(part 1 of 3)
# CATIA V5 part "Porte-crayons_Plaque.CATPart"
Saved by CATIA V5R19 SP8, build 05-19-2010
Part number: Plaque_Pot_Crayons
Material "Bleu vert": density 7860 kg/m3, Young's modulus 2e+11 Pa, Poisson ratio 0.266
Bounding box of the stored display mesh (mm): x -3 to 0, y -80 to 70, z 0 to 100
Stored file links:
  D:\Documents\1_Travail\1 - ac-limoges.fr\OneDrive - ac-limoges.fr\STI2D_Turgot\3 - Supports\Pot_à_Crayons\Maquette numérique\Maquette_eleve\Porte-crayons_Plaque.CATPart
  D:\Documents\1_Travail\1 - ac-limoges.fr\OneDrive - ac-limoges.fr\STI2D_Turgot\3 - Supports\Pot_à_Crayons\Maquette numérique\Maquette_eleve\Pot_Crayons.CATProduct
  D:\Documents\1_Travail\1 - ac-limoges.fr\OneDrive - ac-limoges.fr\STI2D_Turgot\3 - Supports\Pot_à_Crayons\Maquette numérique\Maquette_eleve\Porte-crayons_Pieds.CATPart
  D:\Documents\1_Travail\1 - ac-limoges.fr\OneDrive - ac-limoges.fr\STI2D_Turgot\3 - Supports\Pot_à_Crayons\Maquette numérique\Porte-crayons.CATPart
  C:\Program Files\Dassault Systemes\B19\win_b64\startup\materials\French\Catalog.CATMaterial
  D:\Documents\1_Travail\1 - ac-limoges.fr\OneDrive - ac-limoges.fr\STI2D_Turgot\3 - Supports\Pot_à_Crayons\Maquette numérique\Maquette_eleve\0-Pot_Crayons.CATProduct
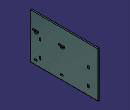
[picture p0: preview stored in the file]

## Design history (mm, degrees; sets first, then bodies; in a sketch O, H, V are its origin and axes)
SheetMetalParameters1: Thickness 3, BendRadius 4, KFactor 0.356492 {= log(min(100,max(20*SheetMetalParameters1.BendRadius,SheetMetalParameters1.Thickness)/SheetMetalParameters1.Thickness))/log(100)/2}, ReliefRadialLength 1, ReliefAxialLength 2, MinimumBendRadius 0
Set1
  DatumSurface1 to DatumSurface7: linked copy from another document
Body1 "Plaque" (main body), material "Bleu vert"
  AxisSystem1: origin (0, 0, 0), X (1, 0, 0), Y (0, 1, 0), Z (0, 0, 1)
  Sketch1 on YZ plane of AxisSystem1, origin (0, 0, 0), H (0, 1, 0), V (0, 0, 1)
    point P1 (0, 50)
    line L1 (70, 100) -> (70, 0)
    line L2 (70, 0) -> (-80, 0)
    line L3 (-80, 0) -> (-80, 100)
    line L4 (-80, 100) -> (70, 100)
    distance L4 L2 = 100
    distance V L1 = 70
    distance L3 V = 80
    vertical: L1 V, L3 V
    horizontal: L2 H, L4 H
    equidistance: L2 L4 P1
    coincidence: P1 V, L2 H
  Wall1: Thickness 3, Profile Sketch1
  Sketch2 on face of Wall1, origin (0, 0, 0), H (0, 1, 0), V (0, 0, 1)
    line L1 (-72, 64) -> (-72, 60)
    line L2 (-72, 60) -> (-66, 60)
    line L3 (-66, 60) -> (-66, 64)
    line L4 (-66, 64) -> (-62.5, 64)
    line L5 (-62.5, 64) -> (-62.5, 67)
    line L6 (-62.5, 67) -> (-75.5, 67)
    line L7 (-75.5, 67) -> (-75.5, 64)
    line L8 (-75.5, 64) -> (-72, 64)
    line L9 (-66, 8) -> (-72, 8)
    line L10 (-72, 8) -> (-72, 11)
    line L11 (-72, 11) -> (-66, 11)
    line L12 (-66, 11) -> (-66, 8)
    reference intersected line E1 (-72, 60) -> (-72, 63) from face of DatumSurface1
    reference intersected line E2 through (0, 63) direction (1, 0) from face of DatumSurface2
    reference intersected line E3 through (0, 11) direction (-1, 0) from face of DatumSurface3
    distance L6 L8 = 3 {= SheetMetalParameters1.Thickness}
    distance L8 L2 = 4 {= `détruit_LENGTH` +Sketch2.distance(L6 L8)}
    distance L1 L3 = 6 {= SheetMetalParameters1.Thickness *2}
    distance L11 L9 = 3 {= SheetMetalParameters1.Thickness}
    distance L7 L1 = 3.5 {= SheetMetalParameters1.Thickness +0.5mm}
    distance L8 E2 = 1
    distance L5 L3 = 3.5 {= SheetMetalParameters1.Thickness +0.5mm}
    horizontal: L2 H, L4 H, L8 H, L9 H, L11 H
    vertical: L1 V, L3 V, L5 V, L7 V, L10 V, L12 V
    coincidence: L4 L8, L12 L3, L1 L10, L1 E1, L11 E3
  CutOut1 "Découpe Accroche Ratelier": Direction Sketch2, EndLimit through (limit type 2), Orientation true, Profile Sketch2, StartLimit through (limit type 2)
  RectPattern1: of CutOut1, direction 1 instances 2, spacing 58, along edge [face of Wall1 | face of Wall1]
  Sketch3 on face of Wall1, origin (-3, 0, 0), H (0, -1, 0), V (0, 0, 1)
    line L1 (57, 57) -> (60, 57)
    line L2 (60, 57) -> (60, 51)
    line L3 (60, 51) -> (57, 51)
    line L4 (57, 51) -> (57, 57)
    point P5 (57, 21)
    line L5 (57, 21) -> (60, 21)
    line L6 (60, 21) -> (60, 15)
    line L7 (60, 15) -> (57, 15)
    line L8 (57, 15) -> (57, 21)
    point P7 (60, 15)
    point P9 (-50, 57)
    line L9 (-50, 57) -> (-47, 57)
    line L10 (-47, 57) -> (-47, 51)
    line L11 (-47, 51) -> (-50, 51)
    line L12 (-50, 51) -> (-50, 57)
    point P11 (-47, 51)
    point P13 (-50, 21)
    line L13 (-50, 21) -> (-47, 21)
    line L14 (-47, 21) -> (-47, 15)
    line L15 (-47, 15) -> (-50, 15)
    line L16 (-50, 15) -> (-50, 21)
    point P15 (-47, 15)
    reference intersected line E1 through (60, 0) direction (0, 1) from face of DatumSurface4
    reference intersected line E2 through (-50, 0) direction (0, 1) from face of DatumSurface5
    reference intersected line E3 (57, 57) -> (60, 57) from face of DatumSurface6
    reference intersected line E4 (57, 21) -> (60, 21) from face of DatumSurface7
    distance L4 L2 = 3 {= SheetMetalParameters1.Thickness}
    distance L12 L10 = 3 {= SheetMetalParameters1.Thickness}
    distance L1 L3 = 6 {= SheetMetalParameters1.Thickness *2}
    distance L5 L7 = 6 {= Sketch3.distance(L1 L3)}
    horizontal: L1 H, L3 H, L5 H, L7 H, L9 H, L11 H, L13 H, L15 H
    vertical: L2 V, L4 V, L6 V, L8 V, L10 V, L12 V, L14 V, L16 V
    coincidence: P5 L4, P7 L2, P9 L1, P11 L3, P13 L12, P13 L5, P15 L10, P15 L7, L2 E1, L12 E2, L1 E3, L5 E4
  CutOut2 "Découpe Accroche pieds": Direction Sketch3, EndLimit through (limit type 2), Orientation false, Profile Sketch3, StartLimit through (limit type 2)
  Sketch4 on face of Wall1, origin (-3, 0, 0), H (0, -1, 0), V (0, 0, 1)
    arc A1 centre (45.9101, 91.2592) radius 3.3 from (48.2435, 93.5926) to (48.0217, 93.7951) ccw
    line L1 (41.5489, 89.0193) -> (46.9279, 94.3983)
    line L2 (37.3062, 89.0193) -> (42.7281, 94.4411)
    line L3 (47.8494, 95.3198) -> (50.1527, 97.6231)
    line L4 (50.1527, 97.6231) -> (52.3096, 95.4662)
    line L5 (56.941, 95.0776) -> (62.1382, 89.8803)
    line L6 (64.6838, 83.0921) -> (62.3805, 80.7888)
    line L7 (61.5018, 75.6675) -> (54.7136, 68.8792)
    line L8 (49.5922, 68.0006) -> (47.2889, 65.6973)
    line L9 (47.2889, 65.6973) -> (45.132, 67.8542)
    line L10 (40.5007, 68.2429) -> (33.6743, 75.0693)
    arc A2 centre (43.0463, 70.7884) radius 2.4 from (41.3492, 69.0914) to (44.2652, 68.721) ccw
    line L11 (48.3496, 68.8792) -> (47.2889, 69.9399)
    line L12 (46.111, 89.3388) -> (49.3042, 92.532)
    arc A3 centre (51.5316, 72.0612) radius 4.5 from (48.3496, 68.8792) to (48.5688, 68.6742) ccw
    arc A4 centre (58.3198, 78.8495) radius 4.5 from (61.5018, 75.6675) to (62.3805, 80.7888) ccw
    line L13 (49.092, 94.4411) -> (50.1527, 93.3805)
    arc A5 centre (45.9101, 91.2592) radius 4.5 from (49.0921, 94.4412) to (48.8729, 94.6462) ccw
    line L14 (37.3062, 89.0193) -> (38.1548, 88.1708)
    line L15 (38.1548, 88.1708) -> (43.5766, 93.5926)
    line L16 (48.2435, 93.5926) -> (49.3042, 92.532)
    arc A6 centre (58.3198, 78.8495) radius 3.3 from (60.6533, 76.516) to (61.4589, 79.8673) ccw
    line L17 (60.6533, 76.516) -> (53.865, 69.7278)
    arc A7 centre (51.5316, 72.0612) radius 3.3 from (49.1981, 69.7278) to (49.4199, 69.5253) ccw
    line L18 (49.1981, 69.7278) -> (48.1375, 70.7884)
    line L19 (43.0081, 75.9178) -> (42.1595, 75.0693)
    line L20 (48.8728, 94.6462) -> (50.1527, 95.9261)
    line L21 (50.1527, 95.9261) -> (51.4255, 94.6533)
    line L22 (62.9867, 83.0921) -> (61.7068, 81.8122)
    arc A8 centre (54.3953, 92.532) radius 2.4 from (56.0924, 94.229) to (53.1764, 94.5994) ccw
    line L23 (48.5688, 68.6742) -> (47.2889, 67.3943)
    line L24 (47.2889, 67.3943) -> (46.0161, 68.6671)
    line L25 (38.7654, 75.9178) -> (37.9169, 75.0693)
    line L26 (41.3492, 69.0914) -> (34.5228, 75.9178)
    line L27 (34.5228, 75.9178) -> (33.6743, 75.0693)
    arc A9 centre (43.0463, 70.7884) radius 3.6 from (40.5007, 68.2428) to (45.132, 67.8542) ccw
    line L28 (46.111, 89.3388) -> (46.9595, 88.4903)
    line L29 (46.9595, 88.4903) -> (50.1527, 91.6834)
    line L30 (56.0924, 94.229) -> (61.2896, 89.0318)
    line L31 (60.8654, 85.2134) -> (59.5926, 83.9406)
    line L32 (61.7139, 84.3649) -> (60.4411, 83.0921)
    line L33 (50.1527, 93.3805) -> (51.4255, 94.6533)
    line L34 (51.0012, 92.532) -> (52.274, 93.8048)
    line L35 (61.4589, 79.8673) -> (50.5138, 68.9221)
    line L36 (60.8557, 80.9611) -> (49.4199, 69.5253)
    line L37 (59.5926, 82.2436) -> (48.1375, 70.7884)
    line L38 (58.7441, 83.0921) -> (47.2889, 71.637)
    line L39 (27.7565, 74.4489) -> (29.2431, 74.4489)
    line L40 (29.2431, 74.4489) -> (29.236, 74.5144)
    line L41 (29.236, 74.5144) -> (29.2267, 74.5766)
    line L42 (29.2267, 74.5766) -> (29.2151, 74.6354)
    line L43 (29.2151, 74.6354) -> (29.2014, 74.6908)
    line L44 (29.2014, 74.6908) -> (29.1854, 74.7428)
    line L45 (29.1854, 74.7428) -> (29.1673, 74.7915)
    line L46 (29.1673, 74.7915) -> (29.1469, 74.8369)
    line L47 (29.1469, 74.8369) -> (29.1244, 74.8789)
    line L48 (29.1244, 74.8789) -> (29.0996, 74.9175)
    line L49 (29.0996, 74.9175) -> (29.0726, 74.9528)
    line L50 (29.0726, 74.9528) -> (29.0282, 75.0023)
    line L51 (29.0282, 75.0023) -> (28.9813, 75.0466)
    line L52 (28.9813, 75.0466) -> (28.9318, 75.0858)
    line L53 (28.9318, 75.0858) -> (28.8797, 75.1197)
    line L54 (28.8797, 75.1197) -> (28.8251, 75.1483)
    line L55 (28.8251, 75.1483) -> (28.7679, 75.1718)
    line L56 (28.7679, 75.1718) -> (28.7081, 75.19)
    line L57 (28.7081, 75.19) -> (28.6458, 75.2031)
    line L58 (28.6458, 75.2031) -> (28.581, 75.2109)
    line L59 (28.581, 75.2109) -> (28.5136, 75.2135)
    line L60 (28.5136, 75.2135) -> (28.4524, 75.2114)
    line L61 (28.4524, 75.2114) -> (28.3932, 75.2052)
    line L62 (28.3932, 75.2052) -> (28.336, 75.1948)
    line L63 (28.336, 75.1948) -> (28.2808, 75.1802)
    line L64 (28.2808, 75.1802) -> (28.2275, 75.1615)
    line L65 (28.2275, 75.1615) -> (28.1762, 75.1386)
    line L66 (28.1762, 75.1386) -> (28.1269, 75.1116)
    line L67 (28.1269, 75.1116) -> (28.0796, 75.0804)
    line L68 (28.0796, 75.0804) -> (28.0343, 75.045)
    line L69 (28.0343, 75.045) -> (27.9909, 75.0055)
    line L70 (27.9909, 75.0055) -> (27.9505, 74.9624)
    line L71 (27.9505, 74.9624) -> (27.9138, 74.9166)
    line L72 (27.9138, 74.9166) -> (27.8809, 74.868)
    line L73 (27.8809, 74.868) -> (27.8517, 74.8165)
    line L74 (27.8517, 74.8165) -> (27.8264, 74.7623)
    line L75 (27.8264, 74.7623) -> (27.8049, 74.7052)
    line L76 (27.8049, 74.7052) -> (27.7871, 74.6454)
    line L77 (27.7871, 74.6454) -> (27.7731, 74.5827)
    line L78 (27.7731, 74.5827) -> (27.763, 74.5172)
    line L79 (27.763, 74.5172) -> (27.7565, 74.4489)
    line L80 (24.8511, 74.2409) -> (24.8532, 74.1389)
    line L81 (24.8532, 74.1389) -> (24.8595, 74.0426)
    line L82 (24.8595, 74.0426) -> (24.8699, 73.952)
    line L83 (24.8699, 73.952) -> (24.8844, 73.867)
    line L84 (24.8844, 73.867) -> (24.9031, 73.7877)
    line L85 (24.9031, 73.7877) -> (24.926, 73.7141)
    line L86 (24.926, 73.7141) -> (24.9531, 73.6462)
    line L87 (24.9531, 73.6462) -> (24.9843, 73.5839)
    line L88 (24.9843, 73.5839) -> (25.0197, 73.5273)
    line L89 (25.0197, 73.5273) -> (25.0592, 73.4763)
    line L90 (25.0592, 73.4763) -> (25.1019, 73.4306)
    line L91 (25.1019, 73.4306) -> (25.1466, 73.3896)
    line L92 (25.1466, 73.3896) -> (25.1935, 73.3535)
    line L93 (25.1935, 73.3535) -> (25.2425, 73.3223)
    line L94 (25.2425, 73.3223) -> (25.2936, 73.2958)
    line L95 (25.2936, 73.2958) -> (25.3468, 73.2741)
    line L96 (25.3468, 73.2741) -> (25.4021, 73.2573)
    line L97 (25.4021, 73.2573) -> (25.4595, 73.2452)
    line L98 (25.4595, 73.2452) -> (25.519, 73.238)
    line L99 (25.519, 73.238) -> (25.5806, 73.2356)
    line L100 (25.5806, 73.2356) -> (25.6418, 73.238)
    line L101 (25.6418, 73.238) -> (25.7009, 73.2452)
    line L102 (25.7009, 73.2452) -> (25.7581, 73.2572)
    line L103 (25.7581, 73.2572) -> (25.8133, 73.2739)
    line L104 (25.8133, 73.2739) -> (25.8664, 73.2955)
    line L105 (25.8664, 73.2955) -> (25.9175, 73.3218)
    line L106 (25.9175, 73.3218) -> (25.9667, 73.3529)
    line L107 (25.9667, 73.3529) -> (26.0138, 73.3888)
    line L108 (26.0138, 73.3888) -> (26.0589, 73.4295)
    line L109 (26.0589, 73.4295) -> (26.102, 73.475)
    line L110 (26.102, 73.475) -> (26.142, 73.5256)
    line L111 (26.142, 73.5256) -> (26.1779, 73.5817)
    line L112 (26.1779, 73.5817) -> (26.2094, 73.6431)
    line L113 (26.2094, 73.6431) -> (26.2368, 73.7101)
    line L114 (26.2368, 73.7101) -> (26.26, 73.7824)
    line L115 (26.26, 73.7824) -> (26.2789, 73.8602)
    line L116 (26.2789, 73.8602) -> (26.2937, 73.9435)
    line L117 (26.2937, 73.9435) -> (26.3042, 74.0321)
    line L118 (26.3042, 74.0321) -> (26.3105, 74.1263)
    line L119 (26.3105, 74.1263) -> (26.3126, 74.2258)
    line L120 (26.3126, 74.2258) -> (26.3105, 74.3212)
    line L121 (26.3105, 74.3212) -> (26.3039, 74.4117)
    line L122 (26.3039, 74.4117) -> (26.2931, 74.4975)
    line L123 (26.2931, 74.4975) -> (26.2779, 74.5784)
    line L124 (26.2779, 74.5784) -> (26.2584, 74.6545)
    line L125 (26.2584, 74.6545) -> (26.2346, 74.7258)
    line L126 (26.2346, 74.7258) -> (26.2064, 74.7923)
    line L127 (26.2064, 74.7923) -> (26.1738, 74.8539)
    line L128 (26.1738, 74.8539) -> (26.137, 74.9108)
    line L129 (26.137, 74.9108) -> (26.0958, 74.9628)
    line L130 (26.0958, 74.9628) -> (26.0515, 75.01)
    line L131 (26.0515, 75.01) -> (26.0055, 75.0522)
    line L132 (26.0055, 75.0522) -> (25.9577, 75.0894)
    line L133 (25.9577, 75.0894) -> (25.9081, 75.1217)
    line L134 (25.9081, 75.1217) -> (25.8567, 75.1489)
    line L135 (25.8567, 75.1489) -> (25.8035, 75.1713)
    line L136 (25.8035, 75.1713) -> (25.7486, 75.1887)
    line L137 (25.7486, 75.1887) -> (25.6919, 75.2011)
    line L138 (25.6919, 75.2011) -> (25.6334, 75.2085)
    line L139 (25.6334, 75.2085) -> (25.5731, 75.211)
    line L140 (25.5731, 75.211) -> (25.5138, 75.2085)
    line L141 (25.5138, 75.2085) -> (25.4564, 75.2012)
    line L142 (25.4564, 75.2012) -> (25.4007, 75.189)
    line L143 (25.4007, 75.189) -> (25.3469, 75.1719)
    line L144 (25.3469, 75.1719) -> (25.2948, 75.1499)
    line L145 (25.2948, 75.1499) -> (25.2446, 75.123)
    line L146 (25.2446, 75.123) -> (25.1962, 75.0912)
    line L147 (25.1962, 75.0912) -> (25.1495, 75.0546)
    line L148 (25.1495, 75.0546) -> (25.1047, 75.013)
    line L149 (25.1047, 75.013) -> (25.0617, 74.9666)
    line L150 (25.0617, 74.9666) -> (25.0217, 74.9153)
    line L151 (25.0217, 74.9153) -> (24.9859, 74.8593)
    line L152 (24.9859, 74.8593) -> (24.9543, 74.7986)
    line L153 (24.9543, 74.7986) -> (24.927, 74.7331)
    line L154 (24.927, 74.7331) -> (24.9038, 74.663)
    line L155 (24.9038, 74.663) -> (24.8848, 74.588)
    line L156 (24.8848, 74.588) -> (24.8701, 74.5083)
    line L157 (24.8701, 74.5083) -> (24.8595, 74.4239)
    line L158 (24.8595, 74.4239) -> (24.8533, 74.3347)
    line L159 (24.8533, 74.3347) -> (24.8511, 74.2409)
    line L160 (22.0009, 74.1932) -> (22.0031, 74.0935)
    line L161 (22.0031, 74.0935) -> (22.0098, 73.9989)
    line L162 (22.0098, 73.9989) -> (22.021, 73.9095)
    line L163 (22.021, 73.9095) -> (22.0366, 73.8252)
    line L164 (22.0366, 73.8252) -> (22.0567, 73.7461)
    line L165 (22.0567, 73.7461) -> (22.0812, 73.6721)
    line L166 (22.0812, 73.6721) -> (22.1102, 73.6032)
    line L167 (22.1102, 73.6032) -> (22.1437, 73.5395)
    line L168 (22.1437, 73.5395) -> (22.1816, 73.4808)
    line L169 (22.1816, 73.4808) -> (22.224, 73.4274)
    line L170 (22.224, 73.4274) -> (22.2698, 73.3791)
    line L171 (22.2698, 73.3791) -> (22.3178, 73.3358)
    line L172 (22.3178, 73.3358) -> (22.3682, 73.2976)
    line L173 (22.3682, 73.2976) -> (22.4209, 73.2646)
    line L174 (22.4209, 73.2646) -> (22.4759, 73.2366)
    line L175 (22.4759, 73.2366) -> (22.5332, 73.2137)
    line L176 (22.5332, 73.2137) -> (22.5928, 73.1959)
    line L177 (22.5928, 73.1959) -> (22.6548, 73.1831)
    line L178 (22.6548, 73.1831) -> (22.719, 73.1755)
    line L179 (22.719, 73.1755) -> (22.7855, 73.173)
    line L180 (22.7855, 73.173) -> (22.8516, 73.1755)
    line L181 (22.8516, 73.1755) -> (22.9154, 73.1832)
    line L182 (22.9154, 73.1832) -> (22.9769, 73.196)
    line L183 (22.9769, 73.196) -> (23.0362, 73.2139)
    line L184 (23.0362, 73.2139) -> (23.0932, 73.2369)
    line L185 (23.0932, 73.2369) -> (23.148, 73.265)
    line L186 (23.148, 73.265) -> (23.2005, 73.2983)
    line L187 (23.2005, 73.2983) -> (23.2508, 73.3366)
    line L188 (23.2508, 73.3366) -> (23.2988, 73.3801)
    line L189 (23.2988, 73.3801) -> (23.3445, 73.4287)
    line L190 (23.3445, 73.4287) -> (23.3869, 73.4825)
    line L191 (23.3869, 73.4825) -> (23.4249, 73.5416)
    line L192 (23.4249, 73.5416) -> (23.4583, 73.6062)
    line L193 (23.4583, 73.6062) -> (23.4873, 73.6761)
    line L194 (23.4873, 73.6761) -> (23.5119, 73.7514)
    line L195 (23.5119, 73.7514) -> (23.5319, 73.832)
    line L196 (23.5319, 73.832) -> (23.5476, 73.9181)
    line L197 (23.5476, 73.9181) -> (23.5587, 74.0094)
    line L198 (23.5587, 74.0094) -> (23.5654, 74.1062)
    line L199 (23.5654, 74.1062) -> (23.5676, 74.2083)
    line L200 (23.5676, 74.2083) -> (23.5654, 74.3046)
    line L201 (23.5654, 74.3046) -> (23.5587, 74.3962)
    line L202 (23.5587, 74.3962) -> (23.5475, 74.483)
    line L203 (23.5475, 74.483) -> (23.5318, 74.565)
    line L204 (23.5318, 74.565) -> (23.5115, 74.6423)
    line L205 (23.5115, 74.6423) -> (23.4869, 74.7147)
    line L206 (23.4869, 74.7147) -> (23.4577, 74.7823)
    line L207 (23.4577, 74.7823) -> (23.424, 74.8452)
    line L208 (23.424, 74.8452) -> (23.3859, 74.9033)
    line L209 (23.3859, 74.9033) -> (23.3433, 74.9566)
    line L210 (23.3433, 74.9566) -> (23.2973, 75.0049)
    line L211 (23.2973, 75.0049) -> (23.2492, 75.0482)
    line L212 (23.2492, 75.0482) -> (23.1988, 75.0863)
    line L213 (23.1988, 75.0863) -> (23.1463, 75.1194)
    line L214 (23.1463, 75.1194) -> (23.0917, 75.1474)
    line L215 (23.0917, 75.1474) -> (23.0348, 75.1703)
    line L216 (23.0348, 75.1703) -> (22.9758, 75.1881)
    line L217 (22.9758, 75.1881) -> (22.9145, 75.2008)
    line L218 (22.9145, 75.2008) -> (22.8511, 75.2085)
    line L219 (22.8511, 75.2085) -> (22.7855, 75.211)
    line L220 (22.7855, 75.211) -> (22.719, 75.2085)
    line L221 (22.719, 75.2085) -> (22.6548, 75.2009)
    line L222 (22.6548, 75.2009) -> (22.5928, 75.1882)
    line L223 (22.5928, 75.1882) -> (22.5332, 75.1705)
    line L224 (22.5332, 75.1705) -> (22.4759, 75.1477)
    line L225 (22.4759, 75.1477) -> (22.4209, 75.1199)
    line L226 (22.4209, 75.1199) -> (22.3682, 75.0869)
    line L227 (22.3682, 75.0869) -> (22.3178, 75.049)
    line L228 (22.3178, 75.049) -> (22.2698, 75.0059)
    line L229 (22.2698, 75.0059) -> (22.224, 74.9578)
    line L230 (22.224, 74.9578) -> (22.1816, 74.9046)
    line L231 (22.1816, 74.9046) -> (22.1437, 74.8462)
    line L232 (22.1437, 74.8462) -> (22.1102, 74.7827)
    line L233 (22.1102, 74.7827) -> (22.0812, 74.7139)
    line L234 (22.0812, 74.7139) -> (22.0567, 74.6401)
    line L235 (22.0567, 74.6401) -> (22.0366, 74.561)
    line L236 (22.0366, 74.561) -> (22.021, 74.4768)
    line L237 (22.021, 74.4768) -> (22.0098, 74.3875)
    line L238 (22.0098, 74.3875) -> (22.0031, 74.2929)
    line L239 (22.0031, 74.2929) -> (22.0009, 74.1932)
    line L240 (41.0493, 79.5425) -> (41.2236, 79.5501)
    line L241 (41.2236, 79.5501) -> (41.3905, 79.5731)
    line L242 (41.3905, 79.5731) -> (41.5499, 79.6112)
    line L243 (41.5499, 79.6112) -> (41.7019, 79.6647)
    line L244 (41.7019, 79.6647) -> (41.8465, 79.7335)
    line L245 (41.8465, 79.7335) -> (41.9836, 79.8175)
    line L246 (41.9836, 79.8175) -> (42.1133, 79.9168)
    line L247 (42.1133, 79.9168) -> (42.2355, 80.0314)
    line L248 (42.2355, 80.0314) -> (42.3503, 80.1613)
    line L249 (42.3503, 80.1613) -> (42.4576, 80.3064)
    line L250 (42.4576, 80.3064) -> (42.5561, 80.4647)
    line L251 (42.5561, 80.4647) -> (42.6442, 80.6341)
    line L252 (42.6442, 80.6341) -> (42.7219, 80.8144)
    line L253 (42.7219, 80.8144) -> (42.7893, 81.0058)
    line L254 (42.7893, 81.0058) -> (42.8462, 81.2082)
    line L255 (42.8462, 81.2082) -> (42.8929, 81.4217)
    line L256 (42.8929, 81.4217) -> (42.9291, 81.6461)
    line L257 (42.9291, 81.6461) -> (42.955, 81.8816)
    line L258 (42.955, 81.8816) -> (42.9706, 82.1282)
    line L259 (42.9706, 82.1282) -> (42.9758, 82.3857)
    line L260 (42.9758, 82.3857) -> (42.9706, 82.6404)
    line L261 (42.9706, 82.6404) -> (42.955, 82.8837)
    line L262 (42.955, 82.8837) -> (42.9291, 83.1155)
    line L263 (42.9291, 83.1155) -> (42.8929, 83.3359)
    line L264 (42.8929, 83.3359) -> (42.8462, 83.5449)
    line L265 (42.8462, 83.5449) -> (42.7893, 83.7425)
    line L266 (42.7893, 83.7425) -> (42.7219, 83.9286)
    line L267 (42.7219, 83.9286) -> (42.6442, 84.1033)
    line L268 (42.6442, 84.1033) -> (42.5561, 84.2666)
    line L269 (42.5561, 84.2666) -> (42.4576, 84.4184)
    line L270 (42.4576, 84.4184) -> (42.3503, 84.5573)
    line L271 (42.3503, 84.5573) -> (42.2355, 84.6815)
    line L272 (42.2355, 84.6815) -> (42.1133, 84.7911)
    line L273 (42.1133, 84.7911) -> (41.9836, 84.8861)
    line L274 (41.9836, 84.8861) -> (41.8465, 84.9665)
    line L275 (41.8465, 84.9665) -> (41.7019, 85.0323)
    line L276 (41.7019, 85.0323) -> (41.5499, 85.0834)
    line L277 (41.5499, 85.0834) -> (41.3905, 85.12)
    line L278 (41.3905, 85.12) -> (41.2236, 85.1419)
    line L279 (41.2236, 85.1419) -> (41.0493, 85.1492)
    line L280 (41.0493, 85.1492) -> (40.875, 85.1419)
    line L281 (40.875, 85.1419) -> (40.7081, 85.12)
    line L282 (40.7081, 85.12) -> (40.5487, 85.0834)
    line L283 (40.5487, 85.0834) -> (40.3967, 85.0323)
    line L284 (40.3967, 85.0323) -> (40.2521, 84.9665)
    line L285 (40.2521, 84.9665) -> (40.115, 84.8861)
    line L286 (40.115, 84.8861) -> (39.9854, 84.7911)
    line L287 (39.9854, 84.7911) -> (39.8631, 84.6815)
    line L288 (39.8631, 84.6815) -> (39.7483, 84.5573)
    line L289 (39.7483, 84.5573) -> (39.641, 84.4184)
    line L290 (39.641, 84.4184) -> (39.5425, 84.2666)
    line L291 (39.5425, 84.2666) -> (39.4544, 84.1033)
    line L292 (39.4544, 84.1033) -> (39.3767, 83.9286)
    line L293 (39.3767, 83.9286) -> (39.3094, 83.7425)
    line L294 (39.3094, 83.7425) -> (39.2524, 83.5449)
    line L295 (39.2524, 83.5449) -> (39.2057, 83.3359)
    line L296 (39.2057, 83.3359) -> (39.1695, 83.1155)
    line L297 (39.1695, 83.1155) -> (39.1436, 82.8837)
    line L298 (39.1436, 82.8837) -> (39.128, 82.6404)
    line L299 (39.128, 82.6404) -> (39.1228, 82.3857)
    line L300 (39.1228, 82.3857) -> (39.128, 82.1282)
    line L301 (39.128, 82.1282) -> (39.1436, 81.8816)
    line L302 (39.1436, 81.8816) -> (39.1695, 81.6461)
    line L303 (39.1695, 81.6461) -> (39.2057, 81.4217)
    line L304 (39.2057, 81.4217) -> (39.2524, 81.2082)
    line L305 (39.2524, 81.2082) -> (39.3094, 81.0058)
    line L306 (39.3094, 81.0058) -> (39.3767, 80.8144)
    line L307 (39.3767, 80.8144) -> (39.4544, 80.6341)
    line L308 (39.4544, 80.6341) -> (39.5425, 80.4647)
    line L309 (39.5425, 80.4647) -> (39.641, 80.3064)
    line L310 (39.641, 80.3064) -> (39.7483, 80.1613)
    line L311 (39.7483, 80.1613) -> (39.8631, 80.0314)
    line L312 (39.8631, 80.0314) -> (39.9854, 79.9168)
    line L313 (39.9854, 79.9168) -> (40.115, 79.8175)
    line L314 (40.115, 79.8175) -> (40.2521, 79.7335)
    line L315 (40.2521, 79.7335) -> (40.3967, 79.6647)
    line L316 (40.3967, 79.6647) -> (40.5487, 79.6112)
    line L317 (40.5487, 79.6112) -> (40.7081, 79.5731)
    line L318 (40.7081, 79.5731) -> (40.875, 79.5501)
    line L319 (40.875, 79.5501) -> (41.0493, 79.5425)
    line L320 (22.8607, 82.6913) -> (23.8705, 82.6913)
    line L321 (23.8705, 82.6913) -> (24.0209, 82.6945)
    line L322 (24.0209, 82.6945) -> (24.1641, 82.7043)
    line L323 (24.1641, 82.7043) -> (24.2999, 82.7206)
    line L324 (24.2999, 82.7206) -> (24.4285, 82.7434)
    line L325 (24.4285, 82.7434) -> (24.5497, 82.7727)
    line L326 (24.5497, 82.7727) -> (24.6636, 82.8085)
    line L327 (24.6636, 82.8085) -> (24.7703, 82.8508)
    line L328 (24.7703, 82.8508) -> (24.8696, 82.8996)
    line L329 (24.8696, 82.8996) -> (24.9616, 82.9549)
    line L330 (24.9616, 82.9549) -> (25.0463, 83.0168)
    line L331 (25.0463, 83.0168) -> (25.1233, 83.085)
    line L332 (25.1233, 83.085) -> (25.1922, 83.1595)
    line L333 (25.1922, 83.1595) -> (25.2529, 83.2402)
    line L334 (25.2529, 83.2402) -> (25.3056, 83.3271)
    line L335 (25.3056, 83.3271) -> (25.3502, 83.4203)
    line L336 (25.3502, 83.4203) -> (25.3867, 83.5198)
    line L337 (25.3867, 83.5198) -> (25.415, 83.6255)
    line L338 (25.415, 83.6255) -> (25.4353, 83.7374)
    line L339 (25.4353, 83.7374) -> (25.4475, 83.8556)
    line L340 (25.4475, 83.8556) -> (25.4515, 83.98)
    line L341 (25.4515, 83.98) -> (25.4474, 84.1037)
    line L342 (25.4474, 84.1037) -> (25.4353, 84.2197)
    line L343 (25.4353, 84.2197) -> (25.415, 84.328)
    line L344 (25.415, 84.328) -> (25.3867, 84.4286)
    line L345 (25.3867, 84.4286) -> (25.3502, 84.5214)
    line L346 (25.3502, 84.5214) -> (25.3056, 84.6066)
    line L347 (25.3056, 84.6066) -> (25.2529, 84.6841)
    line L348 (25.2529, 84.6841) -> (25.1922, 84.7538)
    line L349 (25.1922, 84.7538) -> (25.1233, 84.8159)
    line L350 (25.1233, 84.8159) -> (25.0463, 84.8702)
    line L351 (25.0463, 84.8702) -> (24.9616, 84.9182)
    line L352 (24.9616, 84.9182) -> (24.8696, 84.9611)
    line L353 (24.8696, 84.9611) -> (24.7703, 84.9989)
    line L354 (24.7703, 84.9989) -> (24.6636, 85.0318)
    line L355 (24.6636, 85.0318) -> (24.5497, 85.0595)
    line L356 (24.5497, 85.0595) -> (24.4285, 85.0822)
    line L357 (24.4285, 85.0822) -> (24.2999, 85.0999)
    line L358 (24.2999, 85.0999) -> (24.1641, 85.1125)
    line L359 (24.1641, 85.1125) -> (24.0209, 85.1201)
    line L360 (24.0209, 85.1201) -> (23.8705, 85.1226)
    line L361 (23.8705, 85.1226) -> (22.8607, 85.1226)
    line L362 (22.8607, 85.1226) -> (22.8607, 82.6913)
    line L363 (30.1074, 73.5741) -> (30.0904, 73.6568)
    line L364 (30.1284, 73.4956) -> (30.1074, 73.5741)
    line L365 (30.1532, 73.4213) -> (30.1284, 73.4956)
    line L366 (30.182, 73.3511) -> (30.1532, 73.4213)
    line L367 (30.2148, 73.2851) -> (30.182, 73.3511)
    line L368 (30.2515, 73.2233) -> (30.2148, 73.2851)
    line L369 (30.2921, 73.1656) -> (30.2515, 73.2233)
    line L370 (30.3367, 73.1121) -> (30.2921, 73.1656)
    line L371 (30.3852, 73.0627) -> (30.3367, 73.1121)
    line L372 (30.4376, 73.0175) -> (30.3852, 73.0627)
    line L373 (30.4945, 72.9766) -> (30.4376, 73.0175)
    line L374 (30.5563, 72.9399) -> (30.4945, 72.9766)
    line L375 (30.623, 72.9076) -> (30.5563, 72.9399)
    line L376 (30.6947, 72.8796) -> (30.623, 72.9076)
    line L377 (30.7713, 72.8558) -> (30.6947, 72.8796)
    line L378 (30.8529, 72.8364) -> (30.7713, 72.8558)
    line L379 (30.9394, 72.8213) -> (30.8529, 72.8364)
    line L380 (31.0308, 72.8106) -> (30.9394, 72.8213)
    line L381 (31.1272, 72.8041) -> (31.0308, 72.8106)
    line L382 (31.2285, 72.8019) -> (31.1272, 72.8041)
    line L383 (31.2905, 72.803) -> (31.2285, 72.8019)
    line L384 (31.3512, 72.8063) -> (31.2905, 72.803)
    line L385 (31.4106, 72.8118) -> (31.3512, 72.8063)
    line L386 (31.4687, 72.8194) -> (31.4106, 72.8118)
    line L387 (31.5255, 72.8292) -> (31.4687, 72.8194)
    line L388 (31.581, 72.8412) -> (31.5255, 72.8292)
    line L389 (31.6352, 72.8554) -> (31.581, 72.8412)
    line L390 (31.6881, 72.8717) -> (31.6352, 72.8554)
    line L391 (31.7397, 72.8903) -> (31.6881, 72.8717)
    line L392 (31.79, 72.911) -> (31.7397, 72.8903)
    line L393 (31.8385, 72.9337) -> (31.79, 72.911)
    line L394 (31.8846, 72.9582) -> (31.8385, 72.9337)
    line L395 (31.9284, 72.9846) -> (31.8846, 72.9582)
    line L396 (31.9699, 73.0127) -> (31.9284, 72.9846)
    line L397 (32.0091, 73.0426) -> (31.9699, 73.0127)
    line L398 (32.0459, 73.0743) -> (32.0091, 73.0426)
    line L399 (32.0803, 73.1079) -> (32.0459, 73.0743)
    line L400 (32.1125, 73.1432) -> (32.0803, 73.1079)
    line L401 (32.1423, 73.1804) -> (32.1125, 73.1432)
    line L402 (32.1698, 73.2193) -> (32.1423, 73.1804)
    line L403 (32.1948, 73.2594) -> (32.1698, 73.2193)
    line L404 (32.2172, 73.3001) -> (32.1948, 73.2594)
    line L405 (32.2369, 73.3413) -> (32.2172, 73.3001)
    line L406 (32.254, 73.383) -> (32.2369, 73.3413)
    line L407 (32.2685, 73.4252) -> (32.254, 73.383)
    line L408 (32.2804, 73.4679) -> (32.2685, 73.4252)
    line L409 (32.2896, 73.5112) -> (32.2804, 73.4679)
    line L410 (32.2961, 73.555) -> (32.2896, 73.5112)
    line L411 (32.3001, 73.5994) -> (32.2961, 73.555)
    line L412 (32.3014, 73.6442) -> (32.3001, 73.5994)
    line L413 (32.3003, 73.6896) -> (32.3014, 73.6442)
    line L414 (32.2971, 73.7335) -> (32.3003, 73.6896)
    line L415 (32.2917, 73.7758) -> (32.2971, 73.7335)
    line L416 (32.2842, 73.8167) -> (32.2917, 73.7758)
    line L417 (32.2744, 73.8561) -> (32.2842, 73.8167)
    line L418 (32.2626, 73.8939) -> (32.2744, 73.8561)
    line L419 (32.2486, 73.9303) -> (32.2626, 73.8939)
    line L420 (32.2324, 73.9651) -> (32.2486, 73.9303)
    line L421 (32.2141, 73.9985) -> (32.2324, 73.9651)
    line L422 (32.1936, 74.0303) -> (32.2141, 73.9985)
    line L423 (32.1712, 74.0606) -> (32.1936, 74.0303)
    line L424 (32.1472, 74.0895) -> (32.1712, 74.0606)
    line L425 (32.1216, 74.1169) -> (32.1472, 74.0895)
    line L426 (32.0943, 74.1428) -> (32.1216, 74.1169)
    line L427 (32.0655, 74.1672) -> (32.0943, 74.1428)
    line L428 (32.0349, 74.1902) -> (32.0655, 74.1672)
    line L429 (32.0028, 74.2117) -> (32.0349, 74.1902)
    line L430 (31.969, 74.2316) -> (32.0028, 74.2117)
    line L431 (31.9336, 74.2502) -> (31.969, 74.2316)
    line L432 (31.8966, 74.2672) -> (31.9336, 74.2502)
    line L433 (31.8558, 74.2839) -> (31.8966, 74.2672)
    line L434 (31.8093, 74.3016) -> (31.8558, 74.2839)
    line L435 (31.7569, 74.3202) -> (31.8093, 74.3016)
    line L436 (31.6988, 74.3398) -> (31.7569, 74.3202)
    line L437 (31.6349, 74.3602) -> (31.6988, 74.3398)
    line L438 (31.5652, 74.3816) -> (31.6349, 74.3602)
    line L439 (31.4897, 74.404) -> (31.5652, 74.3816)
    line L440 (31.4084, 74.4272) -> (31.4897, 74.404)
    line L441 (31.3214, 74.4514) -> (31.4084, 74.4272)
    line L442 (31.2285, 74.4765) -> (31.3214, 74.4514)
    line L443 (31.1649, 74.4939) -> (31.2285, 74.4765)
    line L444 (31.1067, 74.51) -> (31.1649, 74.4939)
    line L445 (31.0536, 74.5248) -> (31.1067, 74.51)
    line L446 (31.0059, 74.5383) -> (31.0536, 74.5248)
    line L447 (30.9634, 74.5504) -> (31.0059, 74.5383)
    line L448 (30.9262, 74.5613) -> (30.9634, 74.5504)
    line L449 (30.8942, 74.5709) -> (30.9262, 74.5613)
    line L450 (30.8675, 74.5792) -> (30.8942, 74.5709)
    line L451 (30.8461, 74.5861) -> (30.8675, 74.5792)
    line L452 (30.8299, 74.5918) -> (30.8461, 74.5861)
    line L453 (30.807, 74.6016) -> (30.8299, 74.5918)
    line L454 (30.7853, 74.6119) -> (30.807, 74.6016)
    line L455 (30.7649, 74.6227) -> (30.7853, 74.6119)
    line L456 (30.7457, 74.6339) -> (30.7649, 74.6227)
    line L457 (30.7278, 74.6457) -> (30.7457, 74.6339)
    line L458 (30.7111, 74.658) -> (30.7278, 74.6457)
    line L459 (30.6957, 74.6708) -> (30.7111, 74.658)
    line L460 (30.6815, 74.6841) -> (30.6957, 74.6708)
    line L461 (30.6686, 74.6978) -> (30.6815, 74.6841)
    line L462 (30.6569, 74.7121) -> (30.6686, 74.6978)
    line L463 (30.6465, 74.7264) -> (30.6569, 74.7121)
    line L464 (30.6371, 74.7409) -> (30.6465, 74.7264)
    line L465 (30.6288, 74.7558) -> (30.6371, 74.7409)
    line L466 (30.6216, 74.7711) -> (30.6288, 74.7558)
    line L467 (30.6156, 74.7867) -> (30.6216, 74.7711)
    line L468 (30.6106, 74.8027) -> (30.6156, 74.7867)
    line L469 (30.6067, 74.819) -> (30.6106, 74.8027)
    line L470 (30.604, 74.8357) -> (30.6067, 74.819)
    line L471 (30.6023, 74.8527) -> (30.604, 74.8357)
    line L472 (30.6018, 74.8701) -> (30.6023, 74.8527)
    line L473 (30.6031, 74.8973) -> (30.6018, 74.8701)
    line L474 (30.6071, 74.9238) -> (30.6031, 74.8973)
    line L475 (30.6138, 74.9496) -> (30.6071, 74.9238)
    line L476 (30.623, 74.9747) -> (30.6138, 74.9496)
    line L477 (30.635, 74.9992) -> (30.623, 74.9747)
    line L478 (30.6496, 75.0229) -> (30.635, 74.9992)
    line L479 (30.6669, 75.0459) -> (30.6496, 75.0229)
    line L480 (30.6868, 75.0682) -> (30.6669, 75.0459)
    line L481 (30.7094, 75.0898) -> (30.6868, 75.0682)
    line L482 (30.7346, 75.1107) -> (30.7094, 75.0898)
    line L483 (30.763, 75.1303) -> (30.7346, 75.1107)
    line L484 (30.7949, 75.1477) -> (30.763, 75.1303)
    line L485 (30.8304, 75.1632) -> (30.7949, 75.1477)
    line L486 (30.8694, 75.1765) -> (30.8304, 75.1632)
    line L487 (30.912, 75.1878) -> (30.8694, 75.1765)
    line L488 (30.9581, 75.1971) -> (30.912, 75.1878)
    line L489 (31.0079, 75.2043) -> (30.9581, 75.1971)
    line L490 (31.0611, 75.2094) -> (31.0079, 75.2043)
    line L491 (31.118, 75.2125) -> (31.0611, 75.2094)
    line L492 (31.1784, 75.2135) -> (31.118, 75.2125)
    line L493 (31.2298, 75.2123) -> (31.1784, 75.2135)
    line L494 (31.2789, 75.2089) -> (31.2298, 75.2123)
    line L495 (31.3256, 75.2031) -> (31.2789, 75.2089)
    line L496 (31.3699, 75.1951) -> (31.3256, 75.2031)
    line L497 (31.4118, 75.1847) -> (31.3699, 75.1951)
    line L498 (31.4513, 75.172) -> (31.4118, 75.1847)
    line L499 (31.4885, 75.157) -> (31.4513, 75.172)
    line L500 (31.5233, 75.1397) -> (31.4885, 75.157)
    line L501 (31.5557, 75.1201) -> (31.5233, 75.1397)
    line L502 (31.5857, 75.0982) -> (31.5557, 75.1201)
    line L503 (31.6134, 75.0742) -> (31.5857, 75.0982)
    line L504 (31.6388, 75.0485) -> (31.6134, 75.0742)
    line L505 (31.6619, 75.0209) -> (31.6388, 75.0485)
    line L506 (31.6828, 74.9915) -> (31.6619, 75.0209)
    line L507 (31.7013, 74.9603) -> (31.6828, 74.9915)
    line L508 (31.7176, 74.9273) -> (31.7013, 74.9603)
    line L509 (31.7316, 74.8925) -> (31.7176, 74.9273)
    line L510 (31.7434, 74.8559) -> (31.7316, 74.8925)
    line L511 (31.7528, 74.8175) -> (31.7434, 74.8559)
    line L512 (31.7599, 74.7773) -> (31.7528, 74.8175)
    line L513 (32.2011, 74.8375) -> (31.7599, 74.7773)
    line L514 (32.1919, 74.8881) -> (32.2011, 74.8375)
    line L515 (32.1813, 74.9366) -> (32.1919, 74.8881)
    line L516 (32.1693, 74.983) -> (32.1813, 74.9366)
    line L517 (32.1558, 75.0274) -> (32.1693, 74.983)
    line L518 (32.141, 75.0697) -> (32.1558, 75.0274)
    line L519 (32.1247, 75.1099) -> (32.141, 75.0697)
    line L520 (32.1071, 75.148) -> (32.1247, 75.1099)
    line L521 (32.088, 75.184) -> (32.1071, 75.148)
    line L522 (32.0676, 75.218) -> (32.088, 75.184)
    line L523 (32.0457, 75.2499) -> (32.0676, 75.218)
    line L524 (32.0219, 75.28) -> (32.0457, 75.2499)
    line L525 (31.9956, 75.309) -> (32.0219, 75.28)
    line L526 (31.9669, 75.3366) -> (31.9956, 75.309)
    line L527 (31.9356, 75.363) -> (31.9669, 75.3366)
    line L528 (31.9019, 75.388) -> (31.9356, 75.363)
    line L529 (31.8657, 75.4119) -> (31.9019, 75.388)
    line L530 (31.827, 75.4344) -> (31.8657, 75.4119)
    line L531 (31.7858, 75.4556) -> (31.827, 75.4344)
    line L532 (31.7422, 75.4756) -> (31.7858, 75.4556)
    line L533 (31.696, 75.4943) -> (31.7422, 75.4756)
    line L534 (31.6479, 75.5114) -> (31.696, 75.4943)
    line L535 (31.5982, 75.5268) -> (31.6479, 75.5114)
    line L536 (31.547, 75.5403) -> (31.5982, 75.5268)
    line L537 (31.4943, 75.552) -> (31.547, 75.5403)
    line L538 (31.44, 75.562) -> (31.4943, 75.552)
    line L539 (31.3842, 75.5701) -> (31.44, 75.562)
    line L540 (31.3269, 75.5764) -> (31.3842, 75.5701)
    line L541 (31.2681, 75.5809) -> (31.3269, 75.5764)
    line L542 (31.2077, 75.5836) -> (31.2681, 75.5809)
    line L543 (31.1458, 75.5845) -> (31.2077, 75.5836)
    line L544 (31.1044, 75.584) -> (31.1458, 75.5845)
    line L545 (31.0636, 75.5824) -> (31.1044, 75.584)
    line L546 (31.0233, 75.5797) -> (31.0636, 75.5824)
    line L547 (30.9835, 75.5759) -> (31.0233, 75.5797)
    line L548 (30.9443, 75.571) -> (30.9835, 75.5759)
    line L549 (30.9056, 75.5651) -> (30.9443, 75.571)
    line L550 (30.8674, 75.5581) -> (30.9056, 75.5651)
    line L551 (30.8297, 75.55) -> (30.8674, 75.5581)
    line L552 (30.7926, 75.5409) -> (30.8297, 75.55)
    line L553 (30.756, 75.5306) -> (30.7926, 75.5409)
    line L554 (30.7204, 75.5196) -> (30.756, 75.5306)
    line L555 (30.6863, 75.5081) -> (30.7204, 75.5196)
    line L556 (30.6538, 75.4961) -> (30.6863, 75.5081)
    line L557 (30.6228, 75.4837) -> (30.6538, 75.4961)
    line L558 (30.5933, 75.4708) -> (30.6228, 75.4837)
    line L559 (30.5654, 75.4574) -> (30.5933, 75.4708)
    line L560 (30.539, 75.4435) -> (30.5654, 75.4574)
    line L561 (30.5141, 75.4291) -> (30.539, 75.4435)
    line L562 (30.4907, 75.4143) -> (30.5141, 75.4291)
    line L563 (30.4689, 75.399) -> (30.4907, 75.4143)
    line L564 (30.4414, 75.3784) -> (30.4689, 75.399)
    line L565 (30.4151, 75.3569) -> (30.4414, 75.3784)
    line L566 (30.39, 75.3342) -> (30.4151, 75.3569)
    line L567 (30.366, 75.3106) -> (30.39, 75.3342)
    line L568 (30.3433, 75.2859) -> (30.366, 75.3106)
    line L569 (30.3217, 75.2602) -> (30.3433, 75.2859)
    line L570 (30.3013, 75.2335) -> (30.3217, 75.2602)
    line L571 (30.282, 75.2057) -> (30.3013, 75.2335)
    line L572 (30.2639, 75.1769) -> (30.282, 75.2057)
    line L573 (30.2471, 75.1471) -> (30.2639, 75.1769)
    line L574 (30.2316, 75.1165) -> (30.2471, 75.1471)
    line L575 (30.2177, 75.0854) -> (30.2316, 75.1165)
    line L576 (30.2055, 75.0537) -> (30.2177, 75.0854)
    line L577 (30.1949, 75.0215) -> (30.2055, 75.0537)
    line L578 (30.186, 74.9888) -> (30.1949, 75.0215)
    line L579 (30.1786, 74.9556) -> (30.186, 74.9888)
    line L580 (30.1729, 74.9218) -> (30.1786, 74.9556)
    line L581 (30.1688, 74.8876) -> (30.1729, 74.9218)
    line L582 (30.1664, 74.8528) -> (30.1688, 74.8876)
    line L583 (30.1656, 74.8174) -> (30.1664, 74.8528)
    line L584 (30.1666, 74.7787) -> (30.1656, 74.8174)
    line L585 (30.1696, 74.7406) -> (30.1666, 74.7787)
    line L586 (30.1745, 74.7031) -> (30.1696, 74.7406)
    line L587 (30.1814, 74.6664) -> (30.1745, 74.7031)
    line L588 (30.1903, 74.6304) -> (30.1814, 74.6664)
    line L589 (30.2012, 74.595) -> (30.1903, 74.6304)
    line L590 (30.2141, 74.5603) -> (30.2012, 74.595)
    line L591 (30.229, 74.5262) -> (30.2141, 74.5603)
    line L592 (30.2458, 74.4929) -> (30.229, 74.5262)
    line L593 (30.2646, 74.4602) -> (30.2458, 74.4929)
    line L594 (30.2853, 74.4286) -> (30.2646, 74.4602)
    line L595 (30.3079, 74.3983) -> (30.2853, 74.4286)
    line L596 (30.3324, 74.3695) -> (30.3079, 74.3983)
    line L597 (30.3587, 74.3421) -> (30.3324, 74.3695)
    line L598 (30.3868, 74.3161) -> (30.3587, 74.3421)
    line L599 (30.4168, 74.2915) -> (30.3868, 74.3161)
    line L600 (30.4487, 74.2682) -> (30.4168, 74.2915)
    line L601 (30.4824, 74.2464) -> (30.4487, 74.2682)
    line L602 (30.518, 74.226) -> (30.4824, 74.2464)
    line L603 (30.5554, 74.207) -> (30.518, 74.226)
    line L604 (30.5968, 74.1884) -> (30.5554, 74.207)
    line L605 (30.6443, 74.1691) -> (30.5968, 74.1884)
    line L606 (30.6979, 74.1491) -> (30.6443, 74.1691)
    line L607 (30.7576, 74.1284) -> (30.6979, 74.1491)
    line L608 (30.8233, 74.1071) -> (30.7576, 74.1284)
    line L609 (30.8952, 74.085) -> (30.8233, 74.1071)
    line L610 (30.9731, 74.0623) -> (30.8952, 74.085)
    line L611 (31.0572, 74.039) -> (30.9731, 74.0623)
    line L612 (31.1473, 74.0149) -> (31.0572, 74.039)
    line L613 (31.2435, 73.9902) -> (31.1473, 74.0149)
    line L614 (31.3145, 73.9719) -> (31.2435, 73.9902)
    line L615 (31.3799, 73.9544) -> (31.3145, 73.9719)
    line L616 (31.4398, 73.9375) -> (31.3799, 73.9544)
    line L617 (31.4942, 73.9212) -> (31.4398, 73.9375)
    line L618 (31.5431, 73.9056) -> (31.4942, 73.9212)
    line L619 (31.5865, 73.8906) -> (31.5431, 73.9056)
    line L620 (31.6243, 73.8763) -> (31.5865, 73.8906)
    line L621 (31.6566, 73.8626) -> (31.6243, 73.8763)
    line L622 (31.6835, 73.8496) -> (31.6566, 73.8626)
    line L623 (31.7048, 73.8372) -> (31.6835, 73.8496)
    line L624 (31.73, 73.8191) -> (31.7048, 73.8372)
    line L625 (31.7526, 73.7996) -> (31.73, 73.8191)
    line L626 (31.7726, 73.7788) -> (31.7526, 73.7996)
    line L627 (31.7898, 73.7566) -> (31.7726, 73.7788)
    line L628 (31.8044, 73.7332) -> (31.7898, 73.7566)
    line L629 (31.8164, 73.7085) -> (31.8044, 73.7332)
    line L630 (31.8257, 73.6825) -> (31.8164, 73.7085)
    line L631 (31.8323, 73.6552) -> (31.8257, 73.6825)
    line L632 (31.8363, 73.6265) -> (31.8323, 73.6552)
    line L633 (31.8377, 73.5966) -> (31.8363, 73.6265)
    line L634 (31.8361, 73.5629) -> (31.8377, 73.5966)
    line L635 (31.8316, 73.5302) -> (31.8361, 73.5629)
    line L636 (31.8241, 73.4983) -> (31.8316, 73.5302)
    line L637 (31.8136, 73.4673) -> (31.8241, 73.4983)
    line L638 (31.8, 73.4371) -> (31.8136, 73.4673)
    line L639 (31.7835, 73.4078) -> (31.8, 73.4371)
    line L640 (31.7639, 73.3795) -> (31.7835, 73.4078)
    line L641 (31.7414, 73.3519) -> (31.7639, 73.3795)
    line L642 (31.7158, 73.3253) -> (31.7414, 73.3519)
    line L643 (31.6872, 73.2995) -> (31.7158, 73.3253)
    line L644 (31.6556, 73.2755) -> (31.6872, 73.2995)
    line L645 (31.6207, 73.254) -> (31.6556, 73.2755)
    line L646 (31.5826, 73.235) -> (31.6207, 73.254)
    line L647 (31.5412, 73.2185) -> (31.5826, 73.235)
    line L648 (31.4967, 73.2046) -> (31.5412, 73.2185)
    line L649 (31.449, 73.1932) -> (31.4967, 73.2046)
    line L650 (31.3981, 73.1844) -> (31.449, 73.1932)
    line L651 (31.3439, 73.178) -> (31.3981, 73.1844)
    line L652 (31.2865, 73.1742) -> (31.3439, 73.178)
    line L653 (31.226, 73.173) -> (31.2865, 73.1742)
    line L654 (31.1657, 73.1744) -> (31.226, 73.173)
    line L655 (31.1081, 73.1787) -> (31.1657, 73.1744)
    line L656 (31.0533, 73.1858) -> (31.1081, 73.1787)
    line L657 (31.0012, 73.1958) -> (31.0533, 73.1858)
    line L658 (30.9518, 73.2087) -> (31.0012, 73.1958)
    line L659 (30.9052, 73.2244) -> (30.9518, 73.2087)
    line L660 (30.8613, 73.243) -> (30.9052, 73.2244)
    line L661 (30.8201, 73.2644) -> (30.8613, 73.243)
    line L662 (30.7816, 73.2887) -> (30.8201, 73.2644)
    line L663 (30.7459, 73.3158) -> (30.7816, 73.2887)
    line L664 (30.7129, 73.3457) -> (30.7459, 73.3158)
    line L665 (30.6826, 73.378) -> (30.7129, 73.3457)
    line L666 (30.655, 73.4129) -> (30.6826, 73.378)
    line L667 (30.63, 73.4502) -> (30.655, 73.4129)
    line L668 (30.6077, 73.4901) -> (30.63, 73.4502)
    line L669 (30.5881, 73.5324) -> (30.6077, 73.4901)
    line L670 (30.5712, 73.5773) -> (30.5881, 73.5324)
    line L671 (30.557, 73.6247) -> (30.5712, 73.5773)
    line L672 (30.5455, 73.6746) -> (30.557, 73.6247)
    line L673 (30.5366, 73.727) -> (30.5455, 73.6746)
    line L674 (30.0904, 73.6568) -> (30.5366, 73.727)
    line L675 (29.2168, 73.6638) -> (29.2381, 73.7194)
    line L676 (29.194, 73.6113) -> (29.2168, 73.6638)
    line L677 (29.1699, 73.562) -> (29.194, 73.6113)
    line L678 (29.1442, 73.5157) -> (29.1699, 73.562)
    line L679 (29.1171, 73.4725) -> (29.1442, 73.5157)
    line L680 (29.0886, 73.4325) -> (29.1171, 73.4725)
    line L681 (29.0586, 73.3955) -> (29.0886, 73.4325)
    line L682 (29.0271, 73.3617) -> (29.0586, 73.3955)
    line L683 (28.9942, 73.3309) -> (29.0271, 73.3617)
    line L684 (28.9598, 73.3033) -> (28.9942, 73.3309)
    line L685 (28.924, 73.2785) -> (28.9598, 73.3033)
    line L686 (28.8867, 73.2564) -> (28.924, 73.2785)
    line L687 (28.848, 73.2368) -> (28.8867, 73.2564)
    line L688 (28.8078, 73.2199) -> (28.848, 73.2368)
    line L689 (28.7662, 73.2055) -> (28.8078, 73.2199)
    line L690 (28.7231, 73.1938) -> (28.7662, 73.2055)
    line L691 (28.6785, 73.1847) -> (28.7231, 73.1938)
    line L692 (28.6325, 73.1782) -> (28.6785, 73.1847)
    line L693 (28.5851, 73.1743) -> (28.6325, 73.1782)
    line L694 (28.5362, 73.173) -> (28.5851, 73.1743)
    line L695 (28.4706, 73.1753) -> (28.5362, 73.173)
    line L696 (28.4072, 73.1823) -> (28.4706, 73.1753)
    line L697 (28.346, 73.1939) -> (28.4072, 73.1823)
    line L698 (28.2871, 73.2103) -> (28.346, 73.1939)
    line L699 (28.2303, 73.2312) -> (28.2871, 73.2103)
    line L700 (28.1758, 73.2569) -> (28.2303, 73.2312)
    line L701 (28.1234, 73.2872) -> (28.1758, 73.2569)
    line L702 (28.0733, 73.3222) -> (28.1234, 73.2872)
    line L703 (28.0254, 73.3618) -> (28.0733, 73.3222)
    line L704 (27.9797, 73.4061) -> (28.0254, 73.3618)
    line L705 (27.937, 73.4548) -> (27.9797, 73.4061)
    line L706 (27.8983, 73.5076) -> (27.937, 73.4548)
    line L707 (27.8636, 73.5645) -> (27.8983, 73.5076)
    line L708 (27.8329, 73.6255) -> (27.8636, 73.5645)
    line L709 (27.8061, 73.6906) -> (27.8329, 73.6255)
    line L710 (27.7832, 73.7599) -> (27.8061, 73.6906)
    line L711 (27.7643, 73.8332) -> (27.7832, 73.7599)
    line L712 (27.7494, 73.9107) -> (27.7643, 73.8332)
    line L713 (27.7385, 73.9922) -> (27.7494, 73.9107)
    line L714 (27.7315, 74.0779) -> (27.7385, 73.9922)
    line L715 (29.7169, 74.0779) -> (27.7315, 74.0779)
    line L716 (29.7174, 74.0936) -> (29.7169, 74.0779)
    line L717 (29.7178, 74.1084) -> (29.7174, 74.0936)
    line L718 (29.7182, 74.1224) -> (29.7178, 74.1084)
    line L719 (29.7185, 74.1357) -> (29.7182, 74.1224)
    line L720 (29.7188, 74.1481) -> (29.7185, 74.1357)
    line L721 (29.719, 74.1597) -> (29.7188, 74.1481)
    line L722 (29.7192, 74.1706) -> (29.719, 74.1597)
    line L723 (29.7193, 74.1806) -> (29.7192, 74.1706)
    line L724 (29.7194, 74.1898) -> (29.7193, 74.1806)
    line L725 (29.7194, 74.1982) -> (29.7194, 74.1898)
    line L726 (29.716, 74.3271) -> (29.7194, 74.1982)
    line L727 (29.7058, 74.4501) -> (29.716, 74.3271)
    line L728 (29.6889, 74.5672) -> (29.7058, 74.4501)
    line L729 (29.6652, 74.6783) -> (29.6889, 74.5672)
    line L730 (29.6348, 74.7836) -> (29.6652, 74.6783)
    line L731 (29.5975, 74.8829) -> (29.6348, 74.7836)
    line L732 (29.5535, 74.9763) -> (29.5975, 74.8829)
    line L733 (29.5028, 75.0638) -> (29.5535, 74.9763)
    line L734 (29.4453, 75.1454) -> (29.5028, 75.0638)
    line L735 (29.381, 75.221) -> (29.4453, 75.1454)
    line L736 (29.3113, 75.2901) -> (29.381, 75.221)
    line L737 (29.2378, 75.3519) -> (29.3113, 75.2901)
    line L738 (29.1603, 75.4064) -> (29.2378, 75.3519)
    line L739 (29.0789, 75.4537) -> (29.1603, 75.4064)
    line L740 (28.9937, 75.4936) -> (29.0789, 75.4537)
    line L741 (28.9045, 75.5264) -> (28.9937, 75.4936)
    line L742 (28.8114, 75.5518) -> (28.9045, 75.5264)
    line L743 (28.7144, 75.57) -> (28.8114, 75.5518)
    line L744 (28.6134, 75.5809) -> (28.7144, 75.57)
    line L745 (28.5086, 75.5845) -> (28.6134, 75.5809)
    line L746 (28.4003, 75.5808) -> (28.5086, 75.5845)
    line L747 (28.2962, 75.5697) -> (28.4003, 75.5808)
    line L748 (28.1962, 75.5511) -> (28.2962, 75.5697)
    line L749 (28.1003, 75.5252) -> (28.1962, 75.5511)
    line L750 (28.0085, 75.4918) -> (28.1003, 75.5252)
    line L751 (27.9208, 75.4509) -> (28.0085, 75.4918)
    line L752 (27.8372, 75.4027) -> (27.9208, 75.4509)
    line L753 (27.7577, 75.3471) -> (27.8372, 75.4027)
    line L754 (27.6824, 75.284) -> (27.7577, 75.3471)
    line L755 (27.6111, 75.2135) -> (27.6824, 75.284)
    line L756 (27.5454, 75.1363) -> (27.6111, 75.2135)
    line L757 (27.4866, 75.0531) -> (27.5454, 75.1363)
    line L758 (27.4347, 74.9638) -> (27.4866, 75.0531)
    line L759 (27.3897, 74.8686) -> (27.4347, 74.9638)
    line L760 (27.3517, 74.7673) -> (27.3897, 74.8686)
    line L761 (27.3206, 74.66) -> (27.3517, 74.7673)
    line L762 (27.2963, 74.5467) -> (27.3206, 74.66)
    line L763 (27.2791, 74.4274) -> (27.2963, 74.5467)
    line L764 (27.2687, 74.302) -> (27.2791, 74.4274)
    line L765 (27.2652, 74.1707) -> (27.2687, 74.302)
    line L766 (27.2686, 74.0437) -> (27.2652, 74.1707)
    line L767 (27.2789, 73.9225) -> (27.2686, 74.0437)
    line L768 (27.296, 73.8072) -> (27.2789, 73.9225)
    line L769 (27.32, 73.6976) -> (27.296, 73.8072)
    line L770 (27.3507, 73.5938) -> (27.32, 73.6976)
    line L771 (27.3884, 73.4958) -> (27.3507, 73.5938)
    line L772 (27.4329, 73.4036) -> (27.3884, 73.4958)
    line L773 (27.4842, 73.3171) -> (27.4329, 73.4036)
    line L774 (27.5424, 73.2365) -> (27.4842, 73.3171)
    line L775 (27.6074, 73.1617) -> (27.5424, 73.2365)
    line L776 (27.6782, 73.0933) -> (27.6074, 73.1617)
    line L777 (27.7539, 73.0322) -> (27.6782, 73.0933)
    line L778 (27.8345, 72.9782) -> (27.7539, 73.0322)
    line L779 (27.9198, 72.9315) -> (27.8345, 72.9782)
    line L780 (28.01, 72.8919) -> (27.9198, 72.9315)
    line L781 (28.1051, 72.8595) -> (28.01, 72.8919)
    line L782 (28.205, 72.8343) -> (28.1051, 72.8595)
    line L783 (28.3097, 72.8163) -> (28.205, 72.8343)
    line L784 (28.4193, 72.8055) -> (28.3097, 72.8163)
    line L785 (28.5336, 72.8019) -> (28.4193, 72.8055)
    line L786 (28.6248, 72.8042) -> (28.5336, 72.8019)
    line L787 (28.7125, 72.811) -> (28.6248, 72.8042)
    line L788 (28.797, 72.8223) -> (28.7125, 72.811)
    line L789 (28.8782, 72.838) -> (28.797, 72.8223)
    line L790 (28.956, 72.8583) -> (28.8782, 72.838)
    line L791 (29.0306, 72.8832) -> (28.956, 72.8583)
    line L792 (29.1018, 72.9125) -> (29.0306, 72.8832)
    line L793 (29.1698, 72.9463) -> (29.1018, 72.9125)
    line L794 (29.2344, 72.9847) -> (29.1698, 72.9463)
